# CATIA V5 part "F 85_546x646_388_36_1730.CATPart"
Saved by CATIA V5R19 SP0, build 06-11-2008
Definition: F 85_546x646_388_36_1730
Nomenclature: F 85_546x646_388_36_1730
Description: PART--DESC
Material "Steel": density 7860 kg/m3, Young's modulus 2e+11 Pa, Poisson ratio 0.266, thermal expansion 1.17e-05 1/K
Bounding box of the stored display mesh (mm): x -323 to 323, y -194 to 194, z -274 to -238
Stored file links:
  G:\UTB\Kombinované\Bakalářská práce\Catia\FORMA\F 85_546x646_388_36_1730.CATPart
  D:\Aplikace\CATIA\Nová složka\win_b64\startup\materials\Catalog.CATMaterial
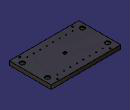
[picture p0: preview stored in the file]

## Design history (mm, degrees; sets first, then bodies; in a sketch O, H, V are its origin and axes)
Body1 "F 85_546646_388_36_1730" (main body)
  Solid1: solid without history
  Sketch1 on face of Solid1, origin (-222.02, -119.1173, -274), H (1, 0, 0), V (0, -1, 0)
    point P1 (12.02, 20.8827)
    reference intersected line E1 through (0, -119.1173) direction (1, 0) from zx-plane
    reference intersected line E2 through (222.02, 0) direction (0, 1) from yz-plane
    distance P1 E1 = 140
    distance P1 E2 = 210
  Hole1: placed by Sketch1, at (-210, -140, -274) direction (0, 0, 1), diameter 9, through (limit type 6)
  Chamfer1: length 0.5, angle 45, on face of Hole1
  RectPattern1: of Hole1, Chamfer1, direction 1 instances 8, spacing 60, along X axis, direction 2 instances 2, spacing 280, along Y axis
  Sketch2 on face of Solid1, origin (-284.7328, -95.9476, -238), H (1, 0, 0), V (0, 1, 0)
    point P1 (5.7328, -21.5524)
    reference intersected line E1 through (0, 95.9476) direction (-1, 0) from Plane1
    reference intersected line E2 through (284.7328, 0) direction (0, 1) from Plane2
    distance P1 E1 = 117.5
    distance P1 E2 = 279
  Hole2: placed by Sketch2, at (-279, -117.5, -238) direction (0, 0, -1), diameter 38, through (limit type 6), counterbore diameter 42, counterbore depth 6
  RectPattern2: of Hole2, direction 1 instances 2, spacing 558, along X axis, direction 2 instances 2, spacing 235, along Y axis
  Plane1: stored without definition
  Plane2: stored without definition
  Sketch3 on face of Solid1, origin (-323, -0.8042, -257.0967), H (0, 1, 0), V (0, 0, -1)
    point P1 (0.8042, -5.0967)
    reference intersected line E1 through (0.8042, 0) direction (0, 1) from zx-plane
    reference projected line E2 (-193.1958, 16.9033) -> (194.8042, 16.9033) from edge [face of Solid1 | face of Solid1]
    distance P1 E2 = 22
    coincidence: P1 E1
  Hole3: placed by Sketch3, at (-323, 0, -252) direction (1, 0, 0), diameter 6.1, depth 7, V-bottom angle 120, countersink depth 1, countersink angle 90
  Sketch4 on face of Solid1, origin (0, 0, -238), H (1, 0, 0), V (0, 1, 0)
    point P1 (0, 0)
    line L1 (14.375, 11.15) -> (14.375, -11.15)
    line L2 (14.375, -11.15) -> (-14.375, -11.15)
    line L3 (-14.375, -11.15) -> (-14.375, 11.15)
    line L4 (-14.375, 11.15) -> (14.375, 11.15)
    reference intersected line E1 through (0, 0) direction (-1, 0) from zx-plane
    reference intersected line E2 through (0, 0) direction (0, 1) from yz-plane
    distance L3 L1 = 28.75
    distance L2 L4 = 22.3
    vertical: L1 V, L3 V
    horizontal: L2 H, L4 H
    equidistance: L1 L3 P1, L2 L4 P1
    coincidence: P1 E1, P1 E2
  Pocket1: profile Sketch4, direction (0, 0, -1), length 8
  Fillet1: radius 5, on edge [face of Pocket1 from Sketch4.L3 | face of Pocket1 from Sketch4.L4]; edge [face of Pocket1 from Sketch4.L2 | face of Pocket1 from Sketch4.L3]; edge [face of Pocket1 from Sketch4.L4 | face of Pocket1 from Sketch4.L1]; edge [face of Pocket1 from Sketch4.L1 | face of Pocket1 from Sketch4.L2]
  Sketch5 on end face of Pocket1, origin (9.1559, 0.6235, -246), H (1, 0, 0), V (0, 1, 0)
    point P1 (-9.1559, -0.6235)
    reference intersected line E1 through (0, -0.6235) direction (-1, 0) from zx-plane
    reference intersected line E2 through (-9.1559, 0) direction (0, 1) from yz-plane
    coincidence: P1 E1, P1 E2
  Hole4: placed by Sketch5, at (0, 0, -246) direction (0, 0, -1), diameter 16.01, through (limit type 6), countersink depth 0.5, countersink angle 90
